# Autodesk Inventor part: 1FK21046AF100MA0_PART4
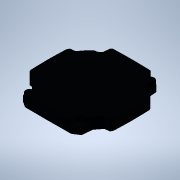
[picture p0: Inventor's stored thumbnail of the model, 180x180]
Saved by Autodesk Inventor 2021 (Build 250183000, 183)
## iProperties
Created: 2025-04
Part Number: 1FK21046AF100MA0_PART4
Material: Generic
Catalog Web Link: www.3dfindit.com
Description: -Servo synchronous motor
Document SubType Name: Modeling
Designer: psAdmin
Mass: 55.5405 g
Surface Area: 149.572 cm^2
Volume: 55.5405 cm^3
Density: 1 g/cm^3
Appearance: PSOLRGB-38-46-56
Category: PARTsolutions
Title: 1FK21046AF100MA0_PART4
Author: Cadenas PARTsolutions
Comments: Servo synchronous motor
Sending System: PARTsolutions
Preprocessor: ST-DEVELOPER v19.3
PSOL_IDENT_0: {$CADENAS_DATA/23d-libs/siemens_ag/_cat_/4f/2b/1fk21046af100ma0.prj},213 {VTYP=3D},{NB=1FK21046AF100
PSOL_IDENT_1: MA0_PART4},{LINA=1FK21046AF100MA0_PART4},{NN=1FK21046AF100MA0_PART4},{NOPRJ=TRUE},{DATE=19.08.2025 1
PSOL_IDENT_2: 4:00:37},{GEOMDATE=30.07.2025 02:01:06},{VERSION=},{LINEID=10},{WBVAR=},{WBNUMERIC=}  {NB=1FK21046AF
PSOL_IDENT_3: 100MA0_PART4},{LINA=1FK21046AF100MA0_PART4},{KT=DUMMY},{PREVIEW=../../../_pool_/cb/72/p_d211_xx_0043
PSOL_IDENT_4: 4j.png},{DESCSHORT=SIMOTICS S-1FK2 HD, SINAMICS S210 3AC 400V-480V, 3.2 Nm, 3000 rpm},{DESCLONG=SIMO
PSOL_IDENT_5: TICS S-1FK2 HD servo motor M0=3.2 Nm; PN = 1 kW at nN=3000 rpm (380-480 V); PN = 0.5 kW at nN=1500 r
PSOL_IDENT_6: pm (200-240 V); with holding brake; degree of protection IP64; cylindrical shaft D19x40mm; absolute
PSOL_IDENT_7: encoder 22-bit + 12-bit multiturn (encoder AM22DQC); with OCC interface; plug size M17, rotatable; S
PSOL_IDENT_8: IMOTICS S-1FK2 servomotorfor a wide range of uses in industrial environments. SIMOTICS S‑1FK2 servom
PSOL_IDENT_9: otors are compact synchronous motors with a high dynamic performance that set themselves apart as a
PSOL_IDENT_10: result of their high power density, degree of protection and overload capability. The motors are ava
PSOL_IDENT_11: ilable in two variants: as High Dynamic variant (highest dynamic performance as a result of the low
PSOL_IDENT_12: intrinsic moment of inertia for applications demanding a high dynamic performance with low moved mas
PSOL_IDENT_13: ses) - and as Compact variant (precise and stable closed-loop control for medium up to large moved m
PSOL_IDENT_14: asses as a result of a medium intrinsic moment of inertia). SIMOTICSS‑1FK2 servomotors fully exploit
PSOL_IDENT_15: their strengths in a system with the SINAMICSS210 frequency converter and simple connection using t
PSOL_IDENT_16: he one cable connection (OCC). Advantages include the short control and positioning times, fast and
PSOL_IDENT_17: precise correction of disturbing quantities as well as stable control with a high dynamic performanc
PSOL_IDENT_18: e. The servo motors can be configured to address a wide range of requirements. For example with and
PSOL_IDENT_19: without holding brake, IP64 or IP65 degree of protection, singleturn or multiturn absolute encoders
PSOL_IDENT_20: - to name just a few. Further, the servomotors are available in different shaft heights extending fr
PSOL_IDENT_21: om 20 to 100. A shaft sealing ring is available to achieve an IP65 degree of protection and for subs
PSOL_IDENT_22: equent mounting at the motor or as spare part. SIMOTICS - the optimum motor for each and every motio
PSOL_IDENT_23: n control application.},{INTNO=195125049673},{SUPPLIERALTNO=1FK2104-6AF10-0MA0},{MANUID=1FK21046AF10
PSOL_IDENT_24: 0MA0},{MANUNAME=Siemens},{MANUTYPEDESC=Synchronous motor 1FK2-HD 3.2 NM},{AAU732=SIMOTICS},{AAO057=S
PSOL_IDENT_25: -1FK2},{AAU734=SIMOTICS S-1FK2 HD servo motor M0=3.2 Nm; PN = 1 kW at nN=3000 rpm (380-480 V); PN =
PSOL_IDENT_26: 0.5 kW at nN=1500 rpm (200-240 V); with holding brake; degree of protection IP64; cylindrical shaft
PSOL_IDENT_27: D19x40mm; absolute encoder 22-bit + 12-bit multiturn (encoder AM22DQC); with OCC interface; plug siz
PSOL_IDENT_28: e M17, rotatable;},{AAW338=Synchronous motor 1FK2-HD 3.2 NM},{AAO742=SIMOTICS},{AAO663=4042948694534
PSOL_IDENT_29: },{NOCUPEROU=1},{PRICEQUANTITY=1},{QUANTITYMIN=1},{QUANTITYINT=1},{CTN=85015220},{COO=DE},{AAO676=1F
PSOL_IDENT_30: K2104-6AF10-0MA0},{AAO677=Siemens AG},{ORDERUNIT=C62},{CONTENTUNIT=C62}
NB: 1FK21046AF100MA0_PART4
NT: Servo synchronous motor
NBSYN: $MANUID._PART4
LINA: 1FK21046AF100MA0_PART4
CATALOG: SIEMENS
PREVIEW: ../../../_pool_/cb/72/p_d211_xx_00434j.png
DESCSHORT: SIMOTICS S-1FK2 HD, SINAMICS S210 3AC 400V-480V, 3.2 Nm, 3000 rpm
DESCLONG: SIMOTICS S-1FK2 HD servo motor M0=3.2 Nm; PN = 1 kW at nN=3000 rpm (380-480 V); PN = 0.5 kW at nN=1500 rpm (200-240 V); with holding brake; degree of protection
INTNO: 195125049673
SUPPLIERALTNO: 1FK2104-6AF10-0MA0
MANUID: 1FK21046AF100MA0
MANUNAME: Siemens
MANUTYPEDESC: Synchronous motor 1FK2-HD 3.2 NM
AAU732: SIMOTICS
AAO057: S-1FK2
AAU734: SIMOTICS S-1FK2 HD servo motor M0=3.2 Nm; PN = 1 kW at nN=3000 rpm (380-480 V); PN = 0.5 kW at nN=1500 rpm (200-240 V); with holding brake; degree of protection
AAW338: Synchronous motor 1FK2-HD 3.2 NM
AAO742: SIMOTICS
AAO663: 4042948694534.0
NOCUPEROU: 1
PRICEQUANTITY: 1
QUANTITYMIN: 1
QUANTITYINT: 1
CTN: 85015220
COO: DE
ARTICLENO: 1FK21046AF100MA0_PART4
BOMINFO: 1FK21046AF100MA0_PART4
CREATOR: CADENAS GmbH
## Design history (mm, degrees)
feature "2025_04_17_14_59_39_0083"
body "Solid1"
